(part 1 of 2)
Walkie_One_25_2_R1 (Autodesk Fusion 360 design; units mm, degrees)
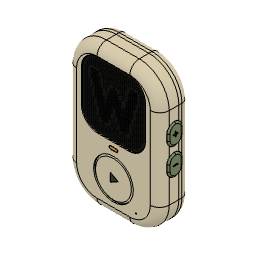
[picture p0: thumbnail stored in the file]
part number: 2026-09-08-11-10-29-672
part number: 2026-09-08-11-10-29-782
part number: 2026-09-08-11-10-30-391
part number: 2026-09-08-11-10-32-289
part number: 2026-09-08-11-10-32-713
part number: 2026-09-08-11-10-32-897
part number: 2026-09-08-11-10-33-663
part number: 2026-09-08-11-10-33-877
description: Part Number
part number: 2026-09-08-11-10-39-665
part number: 2026-09-08-11-10-39-844
part number: 2026-09-08-11-10-40-087
part number: 2026-09-08-11-10-40-640
part number: 2026-09-08-11-10-40-789
part number: 2026-09-08-11-10-41-055
part number: 2026-09-08-11-10-41-421
parameter "body_width" = 90.4 comment "25.2 R1 authoring dimension"
parameter "body_height" = 138.4 comment "25.2 R1 authoring dimension"
parameter "body_depth" = 28.8 comment "25.2 R1 authoring dimension"
parameter "grip_t" = 1.2 comment "25.2 R1 authoring dimension"
parameter "wall_t" = 2 comment "25.2 R1 authoring dimension"
parameter "corner_r" = 29.2 comment "25.2 R1 authoring dimension"
parameter "front_roll" = 9.2 comment "25.2 R1 authoring dimension"
parameter "rear_roll" = 7.2 comment "25.2 R1 authoring dimension"
parameter "play_diameter" = 38 comment "25.2 R1 authoring dimension"
parameter "play_y" = -36 comment "25.2 R1 authoring dimension"
parameter "grille_y" = 27.5 comment "25.2 R1 authoring dimension"
parameter "grille_t" = 0.8 comment "25.2 R1 authoring dimension"
work_plane "WorkPlane1" AlongDistance -13.2 (= "-( body_depth - 2 * grip_t ) / 2") ExtraOffset 0
sketch "rigid_envelope profile" plane through (0, 0, -13.2) normal (0, 0, 1) x axis (1, 0, 0)
  line L1 (-44, 68) -> (44, 68)
  line L2 (-44, -68) -> (-44, 68)
  line L3 (44, -68) -> (-44, -68)
  line L4 (44, 68) -> (44, -68)
  point P2 (44, 68)
  point P3 (-44, 68)
  point P4 (-44, -68)
  dimension "d15" distance P2 P3 = 88 (= "body_width - 2 * grip_t")
  dimension "d16" distance P3 P4 = 136 (= "body_height - 2 * grip_t")
extrude "Extrude1" new body sketch "rigid_envelope profile" along normal blind 26.4 (= "body_depth - 2 * grip_t")
fillet "Fillet1" radius 28 (= "corner_r - grip_t")
fillet "Fillet2" radius 8 (= "front_roll - grip_t")
fillet "Fillet3" radius 6 (= "rear_roll - grip_t")
work_plane "WorkPlane2" AlongDistance -11.2 (= "-( body_depth - 2 * ( grip_t + wall_t ) ) / 2") ExtraOffset 0
sketch "inner_cavity_tool profile" plane through (0, 0, -11.2) normal (0, 0, 1) x axis (1, 0, 0)
  line L1 (-42, 66) -> (42, 66)
  line L2 (-42, -66) -> (-42, 66)
  line L3 (42, -66) -> (-42, -66)
  line L4 (42, 66) -> (42, -66)
  point P2 (42, 66)
  point P3 (-42, 66)
  point P4 (-42, -66)
  dimension "d27" distance P2 P3 = 84 (= "body_width - 2 * ( grip_t + wall_t )")
  dimension "d28" distance P3 P4 = 132 (= "body_height - 2 * ( grip_t + wall_t )")
extrude "Extrude2" new body sketch "inner_cavity_tool profile" along normal blind 22.4 (= "body_depth - 2 * ( grip_t + wall_t )")
fillet "Fillet4" radius 26 (= "corner_r - grip_t - wall_t")
fillet "Fillet5" radius 6 (= "front_roll - grip_t - wall_t")
fillet "Fillet6" radius 4 (= "rear_roll - grip_t - wall_t")
combine "Combine1"
work_plane "WorkPlane3" AlongDistance 14 ExtraOffset 0
sketch "Flat rectangular grille mounting ledge" plane through (0, 0, 14) normal (0, 0, 1) x axis (1, 0, 0)
  line L1 (15, -4.8) -> (-15, -4.8)
  line L2 (31.3, 43.5) -> (31.3, 11.5)
  line L3 (-15, 59.8) -> (15, 59.8)
  line L4 (-31.3, 11.5) -> (-31.3, 43.5)
  arc A1 centre (15, 11.5) radius 16.3 clockwise from (31.3, 11.5) to (15, -4.8)
  arc A2 centre (15, 43.5) radius 16.3 clockwise from (15, 59.8) to (31.3, 43.5)
  arc A3 centre (-15, 43.5) radius 16.3 clockwise from (-31.3, 43.5) to (-15, 59.8)
  arc A4 centre (-15, 11.5) radius 16.3 clockwise from (-15, -4.8) to (-31.3, 11.5)
extrude "Extrude3" cut sketch "Flat rectangular grille mounting ledge" against normal blind 1.28
work_plane "WorkPlane4" AlongDistance 15 ExtraOffset 0
sketch "Full rectangular acoustic aperture" plane through (0, 0, 15) normal (0, 0, 1) x axis (1, 0, 0)
  line L1 (15, -2.3) -> (-15, -2.3)
  line L2 (28.8, 43.5) -> (28.8, 11.5)
  line L3 (-15, 57.3) -> (15, 57.3)
  line L4 (-28.8, 11.5) -> (-28.8, 43.5)
  arc A1 centre (15, 11.5) radius 13.8 clockwise from (28.8, 11.5) to (15, -2.3)
  arc A2 centre (15, 43.5) radius 13.8 clockwise from (15, 57.3) to (28.8, 43.5)
  arc A3 centre (-15, 43.5) radius 13.8 clockwise from (-28.8, 43.5) to (-15, 57.3)
  arc A4 centre (-15, 11.5) radius 13.8 clockwise from (-15, -2.3) to (-28.8, 11.5)
extrude "Extrude4" cut sketch "Full rectangular acoustic aperture" against normal blind 6
work_plane "WorkPlane5" AlongDistance 16 ExtraOffset 0
sketch "Play running clearance" plane through (0, 0, 16) normal (0, 0, 1) x axis (1, 0, 0)
  circle C1 centre (0, -36) radius 19.3
  dimension "d47" diameter C1 = 38.6 (= "play_diameter + 0.6 mm")
extrude "Extrude5" cut sketch "Play running clearance" against normal blind 8
work_plane "WorkPlane6" AlongDistance 11.3 ExtraOffset 0
sketch "Internal play flange relief" plane through (0, 0, 11.3) normal (0, 0, 1) x axis (1, 0, 0)
  circle C1 centre (0, -36) radius 20.5
  dimension "d52" diameter C1 = 41
extrude "Extrude6" cut sketch "Internal play flange relief" against normal blind 2
work_plane "WorkPlane7" AlongDistance 16 ExtraOffset 0
sketch "Status light opening" plane through (0, 0, 16) normal (0, 0, 1) x axis (1, 0, 0)
  line L1 (2.8, -12.05) -> (-2.8, -12.05)
  line L2 (4.3, -10.45) -> (4.3, -10.55)
  line L3 (-2.8, -8.95) -> (2.8, -8.95)
  line L4 (-4.3, -10.55) -> (-4.3, -10.45)
  arc A1 centre (2.8, -10.55) radius 1.5 clockwise from (4.3, -10.55) to (2.8, -12.05)
  arc A2 centre (2.8, -10.45) radius 1.5 clockwise from (2.8, -8.95) to (4.3, -10.45)
  arc A3 centre (-2.8, -10.45) radius 1.5 clockwise from (-4.3, -10.45) to (-2.8, -8.95)
  arc A4 centre (-2.8, -10.55) radius 1.5 clockwise from (-2.8, -12.05) to (-4.3, -10.55)
extrude "Extrude7" cut sketch "Status light opening" against normal blind 8
work_plane "WorkPlane8" AlongDistance -48 ExtraOffset 0
sketch "Left PTT aperture" plane through (-48, 0, 0) normal (1, 0, 0) x axis (0, 0, -1)
  line L1 (0.01, -36.3) -> (-0.01, -36.3)
  line L2 (7.8, 28.51) -> (7.8, -28.51)
  line L3 (-0.01, 36.3) -> (0.01, 36.3)
  line L4 (-7.8, -28.51) -> (-7.8, 28.51)
  arc A1 centre (0.01, -28.51) radius 7.79 clockwise from (7.8, -28.51) to (0.01, -36.3)
  arc A2 centre (0.01, 28.51) radius 7.79 clockwise from (0.01, 36.3) to (7.8, 28.51)
  arc A3 centre (-0.01, 28.51) radius 7.79 clockwise from (-7.8, 28.51) to (-0.01, 36.3)
  arc A4 centre (-0.01, -28.51) radius 7.79 clockwise from (-0.01, -36.3) to (-7.8, -28.51)
extrude "Extrude8" cut sketch "Left PTT aperture" along normal blind 10
work_plane "WorkPlane9" AlongDistance 48 ExtraOffset 0
sketch "Volume aperture 18" plane through (48, 0, 0) normal (1, 0, 0) x axis (0, 0, -1)
  line L1 (0.01, 7.7) -> (-0.01, 7.7)
  line L2 (7.3, 21.01) -> (7.3, 14.99)
  line L3 (-0.01, 28.3) -> (0.01, 28.3)
  line L4 (-7.3, 14.99) -> (-7.3, 21.01)
  arc A1 centre (0.01, 14.99) radius 7.29 clockwise from (7.3, 14.99) to (0.01, 7.7)
  arc A2 centre (0.01, 21.01) radius 7.29 clockwise from (0.01, 28.3) to (7.3, 21.01)
  arc A3 centre (-0.01, 21.01) radius 7.29 clockwise from (-7.3, 21.01) to (-0.01, 28.3)
  arc A4 centre (-0.01, 14.99) radius 7.29 clockwise from (-0.01, 7.7) to (-7.3, 14.99)
extrude "Extrude9" cut sketch "Volume aperture 18" against normal blind 10
work_plane "WorkPlane10" AlongDistance 48 ExtraOffset 0
sketch "Volume aperture -8" plane through (48, 0, 0) normal (1, 0, 0) x axis (0, 0, -1)
  line L1 (0.01, -18.3) -> (-0.01, -18.3)
  line L2 (7.3, -4.99) -> (7.3, -11.01)
  line L3 (-0.01, 2.3) -> (0.01, 2.3)
  line L4 (-7.3, -11.01) -> (-7.3, -4.99)
  arc A1 centre (0.01, -11.01) radius 7.29 clockwise from (7.3, -11.01) to (0.01, -18.3)
  arc A2 centre (0.01, -4.99) radius 7.29 clockwise from (0.01, 2.3) to (7.3, -4.99)
  arc A3 centre (-0.01, -4.99) radius 7.29 clockwise from (-7.3, -4.99) to (-0.01, 2.3)
  arc A4 centre (-0.01, -11.01) radius 7.29 clockwise from (-0.01, -18.3) to (-7.3, -11.01)
extrude "Extrude10" cut sketch "Volume aperture -8" against normal blind 10
work_plane "WorkPlane11" AlongDistance -48 ExtraOffset 0
sketch "USB service aperture" plane through (-48, 0, 0) normal (1, 0, 0) x axis (0, 0, -1)
  line L1 (7.35, -52.75) -> (3.85, -52.75)
  line L2 (9.35, -41.25) -> (9.35, -50.75)
  line L3 (3.85, -39.25) -> (7.35, -39.25)
  line L4 (1.85, -50.75) -> (1.85, -41.25)
  arc A1 centre (7.35, -50.75) radius 2 clockwise from (9.35, -50.75) to (7.35, -52.75)
  arc A2 centre (7.35, -41.25) radius 2 clockwise from (7.35, -39.25) to (9.35, -41.25)
  arc A3 centre (3.85, -41.25) radius 2 clockwise from (1.85, -41.25) to (3.85, -39.25)
  arc A4 centre (3.85, -50.75) radius 2 clockwise from (3.85, -52.75) to (1.85, -50.75)
extrude "Extrude11" cut sketch "USB service aperture" along normal blind 10
work_plane "WorkPlane12" AlongDistance 16 ExtraOffset 0
sketch "Microphone inlet" plane through (0, 0, 16) normal (0, 0, 1) x axis (1, 0, 0)
  circle C1 centre (22, -54) radius 0.6
  dimension "d77" diameter C1 = 1.2
extrude "Extrude12" cut sketch "Microphone inlet" against normal blind 8
work_plane "WorkPlane13" AlongDistance -4.2 ExtraOffset 0
split "Split1" bodies "structural_shell_front"
work_plane "WorkPlane1" AlongDistance -14.4 (= "-( body_depth ) / 2") ExtraOffset 0
sketch "skin_envelope profile" plane through (0, 0, -14.4) normal (0, 0, 1) x axis (1, 0, 0)
  line L1 (-45.2, 69.2) -> (45.2, 69.2)
  line L2 (-45.2, -69.2) -> (-45.2, 69.2)
  line L3 (45.2, -69.2) -> (-45.2, -69.2)
  line L4 (45.2, 69.2) -> (45.2, -69.2)
  point P2 (45.2, 69.2)
  point P3 (-45.2, 69.2)
  point P4 (-45.2, -69.2)
  dimension "d84" distance P2 P3 = 90.4 (= "body_width")
  dimension "d85" distance P3 P4 = 138.4 (= "body_height")
extrude "Extrude1" new body sketch "skin_envelope profile" along normal blind 28.8 (= "body_depth")
fillet "Fillet1" radius 29.2 (= "corner_r")
fillet "Fillet2" radius 9.2 (= "front_roll")
fillet "Fillet3" radius 7.2 (= "rear_roll")
work_plane "WorkPlane2" AlongDistance -13.2 (= "-( body_depth - 2 * grip_t ) / 2") ExtraOffset 0
sketch "skin_inner_tool profile" plane through (0, 0, -13.2) normal (0, 0, 1) x axis (1, 0, 0)
  line L1 (-44, 68) -> (44, 68)
  line L2 (-44, -68) -> (-44, 68)
  line L3 (44, -68) -> (-44, -68)
  line L4 (44, 68) -> (44, -68)
  point P2 (44, 68)
  point P3 (-44, 68)
  point P4 (-44, -68)
  dimension "d96" distance P2 P3 = 88 (= "body_width - 2 * grip_t")
  dimension "d97" distance P3 P4 = 136 (= "body_height - 2 * grip_t")
extrude "Extrude2" new body sketch "skin_inner_tool profile" along normal blind 26.4 (= "body_depth - 2 * grip_t")
fillet "Fillet4" radius 28 (= "corner_r - grip_t")
fillet "Fillet5" radius 8 (= "front_roll - grip_t")
fillet "Fillet6" radius 6 (= "rear_roll - grip_t")
combine "Combine1"
work_plane "WorkPlane3" AlongDistance 16 ExtraOffset 0
sketch "Recessed grille seat" plane through (0, 0, 16) normal (0, 0, 1) x axis (1, 0, 0)
  line L1 (15, -4.8) -> (-15, -4.8)
  line L2 (31.3, 43.5) -> (31.3, 11.5)
  line L3 (-15, 59.8) -> (15, 59.8)
  line L4 (-31.3, 11.5) -> (-31.3, 43.5)
  arc A1 centre (15, 11.5) radius 16.3 clockwise from (31.3, 11.5) to (15, -4.8)
  arc A2 centre (15, 43.5) radius 16.3 clockwise from (15, 59.8) to (31.3, 43.5)
  arc A3 centre (-15, 43.5) radius 16.3 clockwise from (-31.3, 43.5) to (-15, 59.8)
  arc A4 centre (-15, 11.5) radius 16.3 clockwise from (-15, -4.8) to (-31.3, 11.5)
extrude "Extrude3" cut sketch "Recessed grille seat" against normal blind 5
work_plane "WorkPlane4" AlongDistance 16 ExtraOffset 0
sketch "38 mm play opening" plane through (0, 0, 16) normal (0, 0, 1) x axis (1, 0, 0)
  circle C1 centre (0, -36) radius 19.3
  dimension "d112" diameter C1 = 38.6 (= "play_diameter + 0.6 mm")
extrude "Extrude4" cut sketch "38 mm play opening" against normal blind 8
work_plane "WorkPlane5" AlongDistance 16 ExtraOffset 0
sketch "Status lens opening" plane through (0, 0, 16) normal (0, 0, 1) x axis (1, 0, 0)
  line L1 (2.8, -12.05) -> (-2.8, -12.05)
  line L2 (4.3, -10.45) -> (4.3, -10.55)
  line L3 (-2.8, -8.95) -> (2.8, -8.95)
  line L4 (-4.3, -10.55) -> (-4.3, -10.45)
  arc A1 centre (2.8, -10.55) radius 1.5 clockwise from (4.3, -10.55) to (2.8, -12.05)
  arc A2 centre (2.8, -10.45) radius 1.5 clockwise from (2.8, -8.95) to (4.3, -10.45)
  arc A3 centre (-2.8, -10.45) radius 1.5 clockwise from (-4.3, -10.45) to (-2.8, -8.95)
  arc A4 centre (-2.8, -10.55) radius 1.5 clockwise from (-2.8, -12.05) to (-4.3, -10.55)
extrude "Extrude5" cut sketch "Status lens opening" against normal blind 8
work_plane "WorkPlane6" AlongDistance -48 ExtraOffset 0
sketch "PTT soft surround" plane through (-48, 0, 0) normal (1, 0, 0) x axis (0, 0, -1)
  line L1 (0.01, -36.3) -> (-0.01, -36.3)
  line L2 (7.8, 28.51) -> (7.8, -28.51)
  line L3 (-0.01, 36.3) -> (0.01, 36.3)
  line L4 (-7.8, -28.51) -> (-7.8, 28.51)
  arc A1 centre (0.01, -28.51) radius 7.79 clockwise from (7.8, -28.51) to (0.01, -36.3)
  arc A2 centre (0.01, 28.51) radius 7.79 clockwise from (0.01, 36.3) to (7.8, 28.51)
  arc A3 centre (-0.01, 28.51) radius 7.79 clockwise from (-7.8, 28.51) to (-0.01, 36.3)
  arc A4 centre (-0.01, -28.51) radius 7.79 clockwise from (-0.01, -36.3) to (-7.8, -28.51)
extrude "Extrude6" cut sketch "PTT soft surround" along normal blind 10
work_plane "WorkPlane7" AlongDistance 48 ExtraOffset 0
sketch "Volume soft surround 18" plane through (48, 0, 0) normal (1, 0, 0) x axis (0, 0, -1)
  line L1 (0.01, 7.7) -> (-0.01, 7.7)
  line L2 (7.3, 21.01) -> (7.3, 14.99)
  line L3 (-0.01, 28.3) -> (0.01, 28.3)
  line L4 (-7.3, 14.99) -> (-7.3, 21.01)
  arc A1 centre (0.01, 14.99) radius 7.29 clockwise from (7.3, 14.99) to (0.01, 7.7)
  arc A2 centre (0.01, 21.01) radius 7.29 clockwise from (0.01, 28.3) to (7.3, 21.01)
  arc A3 centre (-0.01, 21.01) radius 7.29 clockwise from (-7.3, 21.01) to (-0.01, 28.3)
  arc A4 centre (-0.01, 14.99) radius 7.29 clockwise from (-0.01, 7.7) to (-7.3, 14.99)
extrude "Extrude7" cut sketch "Volume soft surround 18" against normal blind 10
work_plane "WorkPlane8" AlongDistance 48 ExtraOffset 0
sketch "Volume soft surround -8" plane through (48, 0, 0) normal (1, 0, 0) x axis (0, 0, -1)
  line L1 (0.01, -18.3) -> (-0.01, -18.3)
  line L2 (7.3, -4.99) -> (7.3, -11.01)
  line L3 (-0.01, 2.3) -> (0.01, 2.3)
  line L4 (-7.3, -11.01) -> (-7.3, -4.99)
  arc A1 centre (0.01, -11.01) radius 7.29 clockwise from (7.3, -11.01) to (0.01, -18.3)
  arc A2 centre (0.01, -4.99) radius 7.29 clockwise from (0.01, 2.3) to (7.3, -4.99)
  arc A3 centre (-0.01, -4.99) radius 7.29 clockwise from (-7.3, -4.99) to (-0.01, 2.3)
  arc A4 centre (-0.01, -11.01) radius 7.29 clockwise from (-0.01, -18.3) to (-7.3, -11.01)
extrude "Extrude8" cut sketch "Volume soft surround -8" against normal blind 10
work_plane "WorkPlane9" AlongDistance -48 ExtraOffset 0
sketch "USB soft surround" plane through (-48, 0, 0) normal (1, 0, 0) x axis (0, 0, -1)
  line L1 (7.35, -52.75) -> (3.85, -52.75)
  line L2 (9.35, -41.25) -> (9.35, -50.75)
  line L3 (3.85, -39.25) -> (7.35, -39.25)
  line L4 (1.85, -50.75) -> (1.85, -41.25)
  arc A1 centre (7.35, -50.75) radius 2 clockwise from (9.35, -50.75) to (7.35, -52.75)
  arc A2 centre (7.35, -41.25) radius 2 clockwise from (7.35, -39.25) to (9.35, -41.25)
  arc A3 centre (3.85, -41.25) radius 2 clockwise from (1.85, -41.25) to (3.85, -39.25)
  arc A4 centre (3.85, -50.75) radius 2 clockwise from (3.85, -52.75) to (1.85, -50.75)
extrude "Extrude9" cut sketch "USB soft surround" along normal blind 10
work_plane "WorkPlane10" AlongDistance 16 ExtraOffset 0
sketch "Mic soft inlet" plane through (0, 0, 16) normal (0, 0, 1) x axis (1, 0, 0)
  circle C1 centre (22, -54) radius 0.6
  dimension "d137" diameter C1 = 1.2
extrude "Extrude10" cut sketch "Mic soft inlet" against normal blind 8
work_plane "WorkPlane11" AlongDistance -4.2 ExtraOffset 0
split "Split1" bodies "soft_grip_front"
work_plane "WorkPlane12" AlongDistance -14.5 ExtraOffset 0
sketch "Rear wordmark letter 0" plane through (0, 0, -14.5) normal (0, 0, 1) x axis (1, 0, 0)
  line L1 (22.5098, 5.989) -> (24, 5.9969)
  line L2 (21.8467, 3.0702) -> (22.5098, 5.989)
  line L3 (21.5858, 1.7488) -> (21.8467, 3.0702)
  line L4 (21.5574, 1.7102) -> (21.5858, 1.7488)
  line L5 (21.3097, 2.8815) -> (21.5574, 1.7102)
  line L6 (20.5712, 5.9363) -> (21.3097, 2.8815)
  line L7 (20.4693, 5.9969) -> (20.5712, 5.9363)
  line L8 (19.272, 5.9969) -> (20.4693, 5.9969)
  line L9 (19.1608, 5.948) -> (19.272, 5.9969)
  line L10 (18.4886, 3.1851) -> (19.1608, 5.948)
  line L11 (18.1709, 1.7226) -> (18.4886, 3.1851)
  line L12 (18.1426, 1.7532) -> (18.1709, 1.7226)
  line L13 (17.8488, 3.2206) -> (18.1426, 1.7532)
  line L14 (17.2147, 5.9925) -> (17.8488, 3.2206)
  line L15 (15.7262, 5.9934) -> (17.2147, 5.9925)
  line L16 (17.3134, 0.0663) -> (15.7262, 5.9934)
  line L17 (17.4146, 0.0031) -> (17.3134, 0.0663)
  line L18 (18.7615, 0.0031) -> (17.4146, 0.0031)
  line L19 (18.8779, 0.0459) -> (18.7615, 0.0031)
  line L20 (19.656, 3.0908) -> (18.8779, 0.0459)
  line L21 (19.8498, 3.9675) -> (19.656, 3.0908)
  line L22 (19.8776, 3.9612) -> (19.8498, 3.9675)
  line L23 (20.0372, 3.2302) -> (19.8776, 3.9612)
  line L24 (20.849, 0.0394) -> (20.0372, 3.2302)
  line L25 (20.9704, 0.0031) -> (20.849, 0.0394)
  line L26 (22.3173, 0.0031) -> (20.9704, 0.0031)
  line L27 (22.4165, 0.0688) -> (22.3173, 0.0031)
  line L28 (24, 5.9969) -> (22.4165, 0.0688)
extrude "Extrude11" cut sketch "Rear wordmark letter 0" along normal blind 0.35
work_plane "WorkPlane13" AlongDistance -14.5 ExtraOffset 0
sketch "Rear wordmark letter 1" plane through (0, 0, -14.5) normal (0, 0, 1) x axis (1, 0, 0)
  line L1 (12.8659, 5.9969) -> (14.6553, 5.9969)
  line L2 (12.8003, 5.8795) -> (12.8659, 5.9969)
  line L3 (10.7962, 0.1036) -> (12.8003, 5.8795)
  line L4 (10.804, 0.0031) -> (10.7962, 0.1036)
  line L5 (12.2952, 0.0031) -> (10.804, 0.0031)
  line L6 (12.6554, 1.1353) -> (12.2952, 0.0031)
  line L7 (12.7555, 1.2018) -> (12.6554, 1.1353)
  line L8 (14.8384, 1.1953) -> (12.7555, 1.2018)
  line L9 (15.2077, 0.061) -> (14.8384, 1.1953)
  line L10 (15.3147, 0.0031) -> (15.2077, 0.061)
  line L11 (16.6568, 0.0031) -> (15.3147, 0.0031)
  line L12 (16.7012, 0.0777) -> (16.6568, 0.0031)
  line L13 (14.6553, 5.9969) -> (16.7012, 0.0777)
  line L14 (13.7262, 4.6968) -> (13.1548, 2.7224)
  line L15 (13.7664, 4.6698) -> (13.7262, 4.6968)
  line L16 (14.475, 2.292) -> (13.7664, 4.6698)
  line L17 (13.1537, 2.292) -> (14.475, 2.292)
  line L18 (13.0214, 2.3027) -> (13.1537, 2.292)
  line L19 (13.1548, 2.7224) -> (13.0214, 2.3027)
extrude "Extrude12" cut sketch "Rear wordmark letter 1" along normal blind 0.35
work_plane "WorkPlane14" AlongDistance -14.5 ExtraOffset 0
sketch "Rear wordmark letter 2" plane through (0, 0, -14.5) normal (0, 0, 1) x axis (1, 0, 0)
  line L1 (9.2488, 5.9969) -> (10.5892, 5.9969)
  line L2 (9.2062, 5.8906) -> (9.2488, 5.9969)
  line L3 (9.2062, 1.2737) -> (9.2062, 5.8906)
  line L4 (9.1482, 1.1828) -> (9.2062, 1.2737)
  line L5 (6.6163, 1.1828) -> (9.1482, 1.1828)
  line L6 (6.5301, 1.1201) -> (6.6163, 1.1828)
  line L7 (6.5301, 0.0775) -> (6.5301, 1.1201)
  line L8 (6.6045, 0.0031) -> (6.5301, 0.0775)
  line L9 (10.4768, 0.0031) -> (6.6045, 0.0031)
  line L10 (10.5892, 0.0396) -> (10.4768, 0.0031)
  line L11 (10.5892, 5.9969) -> (10.5892, 0.0396)
extrude "Extrude13" cut sketch "Rear wordmark letter 2" along normal blind 0.35
work_plane "WorkPlane15" AlongDistance -14.5 ExtraOffset 0
sketch "Rear wordmark letter 3" plane through (0, 0, -14.5) normal (0, 0, 1) x axis (1, 0, 0)
  line L1 (4.8663, 5.9969) -> (6.2117, 5.9969)
  line L2 (4.8279, 5.8858) -> (4.8663, 5.9969)
  line L3 (4.8279, 3.3445) -> (4.8279, 5.8858)
  line L4 (4.7711, 3.3562) -> (4.8279, 3.3445)
  line L5 (2.6801, 5.8946) -> (4.7711, 3.3562)
  line L6 (2.5787, 5.9969) -> (2.6801, 5.8946)
  line L7 (1.0838, 5.9969) -> (2.5787, 5.9969)
  line L8 (0.9734, 5.9788) -> (1.0838, 5.9969)
  line L9 (3.0999, 3.47) -> (0.9734, 5.9788)
  line L10 (3.111, 3.351) -> (3.0999, 3.47)
  line L11 (0.9567, 0.1159) -> (3.111, 3.351)
  line L12 (0.8956, 0.0031) -> (0.9567, 0.1159)
  line L13 (2.3905, 0.0031) -> (0.8956, 0.0031)
  line L14 (2.5099, 0.0581) -> (2.3905, 0.0031)
  line L15 (4.0421, 2.4497) -> (2.5099, 0.0581)
  line L16 (4.1351, 2.3877) -> (4.0421, 2.4497)
  line L17 (4.8106, 1.5884) -> (4.1351, 2.3877)
  line L18 (4.8279, 1.4453) -> (4.8106, 1.5884)
  line L19 (4.8279, 0.0999) -> (4.8279, 1.4453)
  line L20 (4.8806, 0.0031) -> (4.8279, 0.0999)
  line L21 (6.0765, 0.0031) -> (4.8806, 0.0031)
  line L22 (6.2117, 0.0173) -> (6.0765, 0.0031)
  line L23 (6.2117, 5.9969) -> (6.2117, 0.0173)
extrude "Extrude14" cut sketch "Rear wordmark letter 3" along normal blind 0.35
work_plane "WorkPlane16" AlongDistance -14.5 ExtraOffset 0
sketch "Rear wordmark letter 4" plane through (0, 0, -14.5) normal (0, 0, 1) x axis (1, 0, 0)
  line L1 (0.6637, 0.0031) -> (-0.6775, 0.0031)
  line L2 (0.7055, 0.1104) -> (0.6637, 0.0031)
  line L3 (0.7055, 5.9224) -> (0.7055, 0.1104)
  line L4 (0.631, 5.9969) -> (0.7055, 5.9224)
  line L5 (-0.5613, 5.9969) -> (0.631, 5.9969)
  line L6 (-0.6775, 5.9641) -> (-0.5613, 5.9969)
  line L7 (-0.6775, 0.0031) -> (-0.6775, 5.9641)
extrude "Extrude15" cut sketch "Rear wordmark letter 4" along normal blind 0.35
work_plane "WorkPlane17" AlongDistance -14.5 ExtraOffset 0
sketch "Rear wordmark letter 5" plane through (0, 0, -14.5) normal (0, 0, 1) x axis (1, 0, 0)
  line L1 (-5.5663, 5.9969) -> (-1.2254, 5.9969)
  line L2 (-5.6399, 5.9209) -> (-5.5663, 5.9969)
  line L3 (-5.6399, 4.8731) -> (-5.6399, 5.9209)
  line L4 (-5.546, 4.8172) -> (-5.6399, 4.8731)
  line L5 (-2.702, 4.8172) -> (-5.546, 4.8172)
  line L6 (-2.6083, 4.7612) -> (-2.702, 4.8172)
  line L7 (-2.6083, 3.7134) -> (-2.6083, 4.7612)
  line L8 (-2.6371, 3.5925) -> (-2.6083, 3.7134)
  line L9 (-5.3314, 3.5925) -> (-2.6371, 3.5925)
  line L10 (-5.4094, 3.5207) -> (-5.3314, 3.5925)
  line L11 (-5.4094, 2.4729) -> (-5.4094, 3.5207)
  line L12 (-5.2863, 2.4463) -> (-5.4094, 2.4729)
  line L13 (-2.7416, 2.4463) -> (-5.2863, 2.4463)
  line L14 (-2.6083, 2.4299) -> (-2.7416, 2.4463)
  line L15 (-2.6083, 1.2324) -> (-2.6083, 2.4299)
  line L16 (-2.7084, 1.1828) -> (-2.6083, 1.2324)
  line L17 (-5.5524, 1.1828) -> (-2.7084, 1.1828)
  line L18 (-5.6399, 1.1205) -> (-5.5524, 1.1828)
  line L19 (-5.6399, 0.0727) -> (-5.6399, 1.1205)
  line L20 (-5.5598, 0.0031) -> (-5.6399, 0.0727)
  line L21 (-1.2254, 0.0095) -> (-5.5598, 0.0031)
  line L22 (-1.2254, 5.9969) -> (-1.2254, 0.0095)
extrude "Extrude16" cut sketch "Rear wordmark letter 5" along normal blind 0.35
work_plane "WorkPlane18" AlongDistance -14.5 ExtraOffset 0
sketch "Rear wordmark letter 6" plane through (0, 0, -14.5) normal (0, 0, 1) x axis (1, 0, 0)
  line L1 (-9.0257, 0.4782) -> (-9.267, 0.3033)
  line L2 (-8.9129, 0.5756) -> (-9.0257, 0.4782)
  line L3 (-8.7046, 0.7887) -> (-8.9129, 0.5756)
  line L4 (-8.5212, 1.0235) -> (-8.7046, 0.7887)
  line L5 (-8.3631, 1.2761) -> (-8.5212, 1.0235)
  line L6 (-8.2303, 1.5429) -> (-8.3631, 1.2761)
  line L7 (-8.1238, 1.8213) -> (-8.2303, 1.5429)
  line L8 (-8.0437, 2.1083) -> (-8.1238, 1.8213)
  line L9 (-7.9888, 2.4013) -> (-8.0437, 2.1083)
  line L10 (-7.9573, 2.6977) -> (-7.9888, 2.4013)
  line L11 (-7.9473, 2.9956) -> (-7.9573, 2.6977)
  line L12 (-7.9571, 3.2935) -> (-7.9473, 2.9956)
  line L13 (-7.988, 3.59) -> (-7.9571, 3.2935)
  line L14 (-8.0421, 3.883) -> (-7.988, 3.59)
  line L15 (-8.1213, 4.1704) -> (-8.0421, 3.883)
  line L16 (-8.2268, 4.4491) -> (-8.1213, 4.1704)
  line L17 (-8.3589, 4.7162) -> (-8.2268, 4.4491)
  line L18 (-8.5161, 4.9694) -> (-8.3589, 4.7162)
  line L19 (-8.6988, 5.2048) -> (-8.5161, 4.9694)
  line L20 (-8.7996, 5.3146) -> (-8.6988, 5.2048)
  line L21 (-9.0189, 5.5163) -> (-8.7996, 5.3146)
  line L22 (-9.2596, 5.692) -> (-9.0189, 5.5163)
  line L23 (-9.519, 5.8386) -> (-9.2596, 5.692)
  line L24 (-9.6549, 5.8998) -> (-9.519, 5.8386)
  line L25 (-9.9367, 5.9967) -> (-9.6549, 5.8998)
  line L26 (-10.2279, 6.0594) -> (-9.9367, 5.9967)
  line L27 (-10.5244, 6.0897) -> (-10.2279, 6.0594)
  line L28 (-10.8224, 6.0901) -> (-10.5244, 6.0897)
  line L29 (-11.119, 6.061) -> (-10.8224, 6.0901)
  line L30 (-11.4105, 5.9995) -> (-11.119, 6.061)
  line L31 (-11.6927, 5.9039) -> (-11.4105, 5.9995)
  line L32 (-11.8289, 5.8433) -> (-11.6927, 5.9039)
  line L33 (-12.0887, 5.6975) -> (-11.8289, 5.8433)
  line L34 (-12.3298, 5.5224) -> (-12.0887, 5.6975)
  line L35 (-12.5496, 5.3211) -> (-12.3298, 5.5224)
  line L36 (-12.7454, 5.0965) -> (-12.5496, 5.3211)
  line L37 (-12.916, 4.8522) -> (-12.7454, 5.0965)
  line L38 (-13.0615, 4.5921) -> (-12.916, 4.8522)
  line L39 (-13.1812, 4.3192) -> (-13.0615, 4.5921)
  line L40 (-13.2742, 4.036) -> (-13.1812, 4.3192)
  line L41 (-13.3414, 3.7457) -> (-13.2742, 4.036)
  line L42 (-13.3843, 3.4507) -> (-13.3414, 3.7457)
  line L43 (-13.405, 3.1534) -> (-13.3843, 3.4507)
  line L44 (-13.3983, 2.7064) -> (-13.405, 3.1534)
  line L45 (-13.3675, 2.4099) -> (-13.3983, 2.7064)
  line L46 (-13.3133, 2.1168) -> (-13.3675, 2.4099)
  line L47 (-13.2339, 1.8296) -> (-13.3133, 2.1168)
  line L48 (-13.1282, 1.5509) -> (-13.2339, 1.8296)
  line L49 (-12.9961, 1.2838) -> (-13.1282, 1.5509)
  line L50 (-12.8389, 1.0306) -> (-12.9961, 1.2838)
  line L51 (-12.6564, 0.7951) -> (-12.8389, 1.0306)
  line L52 (-12.4491, 0.5811) -> (-12.6564, 0.7951)
  line L53 (-12.2188, 0.3919) -> (-12.4491, 0.5811)
  line L54 (-11.9687, 0.23) -> (-12.2188, 0.3919)
  line L55 (-11.8368, 0.1606) -> (-11.9687, 0.23)
  line L56 (-11.5614, 0.0469) -> (-11.8368, 0.1606)
  line L57 (-11.2742, -0.0326) -> (-11.5614, 0.0469)
  line L58 (-10.9798, -0.0786) -> (-11.2742, -0.0326)
  line L59 (-10.6822, -0.0935) -> (-10.9798, -0.0786)
  line L60 (-10.3845, -0.0794) -> (-10.6822, -0.0935)
  line L61 (-10.09, -0.0341) -> (-10.3845, -0.0794)
  line L62 (-9.8026, 0.0447) -> (-10.09, -0.0341)
  line L63 (-9.5269, 0.1576) -> (-9.8026, 0.0447)
  line L64 (-9.267, 0.3033) -> (-9.5269, 0.1576)
  line L65 (-11.9033, 1.0644) -> (-11.6633, 0.8867)
  line L66 (-12.0113, 1.1677) -> (-11.9033, 1.0644)
  line L67 (-12.2016, 1.3979) -> (-12.0113, 1.1677)
  line L68 (-12.2838, 1.5228) -> (-12.2016, 1.3979)
  line L69 (-12.4232, 1.7871) -> (-12.2838, 1.5228)
  line L70 (-12.4794, 1.9256) -> (-12.4232, 1.7871)
  line L71 (-12.5649, 2.2119) -> (-12.4794, 1.9256)
  line L72 (-12.6345, 2.6546) -> (-12.5649, 2.2119)
  line L73 (-12.6486, 2.9532) -> (-12.6345, 2.6546)
  line L74 (-12.641, 3.252) -> (-12.6486, 2.9532)
  line L75 (-12.584, 3.6965) -> (-12.641, 3.252)
  line L76 (-12.5089, 3.9858) -> (-12.584, 3.6965)
  line L77 (-12.4585, 4.1265) -> (-12.5089, 3.9858)
  line L78 (-12.3988, 4.2636) -> (-12.4585, 4.1265)
  line L79 (-12.2533, 4.5245) -> (-12.3988, 4.2636)
  line L80 (-12.0741, 4.7635) -> (-12.2533, 4.5245)
  line L81 (-11.8603, 4.9721) -> (-12.0741, 4.7635)
  line L82 (-11.7411, 5.0623) -> (-11.8603, 4.9721)
  line L83 (-11.4826, 5.2119) -> (-11.7411, 5.0623)
  line L84 (-11.2033, 5.3177) -> (-11.4826, 5.2119)
  line L85 (-11.0581, 5.353) -> (-11.2033, 5.3177)
  line L86 (-10.7614, 5.3881) -> (-11.0581, 5.353)
  line L87 (-10.4629, 5.3784) -> (-10.7614, 5.3881)
  line L88 (-10.315, 5.3565) -> (-10.4629, 5.3784)
  line L89 (-10.0271, 5.277) -> (-10.315, 5.3565)
  line L90 (-9.8891, 5.2196) -> (-10.0271, 5.277)
  line L91 (-9.6291, 5.0727) -> (-9.8891, 5.2196)
  line L92 (-9.509, 4.9837) -> (-9.6291, 5.0727)
  line L93 (-9.2932, 4.7773) -> (-9.509, 4.9837)
  line L94 (-9.1981, 4.6619) -> (-9.2932, 4.7773)
  line L95 (-9.034, 4.4123) -> (-9.1981, 4.6619)
  line L96 (-8.9034, 4.1435) -> (-9.034, 4.4123)
  line L97 (-8.8519, 4.0032) -> (-8.9034, 4.1435)
  line L98 (-8.8092, 3.8599) -> (-8.8519, 4.0032)
  line L99 (-8.748, 3.5674) -> (-8.8092, 3.8599)
  line L100 (-8.7152, 3.2703) -> (-8.748, 3.5674)
  line L101 (-8.7062, 2.9715) -> (-8.7152, 3.2703)
  line L102 (-8.7189, 2.6728) -> (-8.7062, 2.9715)
  line L103 (-8.7565, 2.3763) -> (-8.7189, 2.6728)
  line L104 (-8.8234, 2.0851) -> (-8.7565, 2.3763)
  line L105 (-8.8694, 1.9428) -> (-8.8234, 2.0851)
  line L106 (-8.9244, 1.8039) -> (-8.8694, 1.9428)
  line L107 (-9.0618, 1.5385) -> (-8.9244, 1.8039)
  line L108 (-9.2327, 1.2934) -> (-9.0618, 1.5385)
  line L109 (-9.3311, 1.181) -> (-9.2327, 1.2934)
  line L110 (-9.5534, 0.9815) -> (-9.3311, 1.181)
  line L111 (-9.6763, 0.8964) -> (-9.5534, 0.9815)
  line L112 (-9.9407, 0.7574) -> (-9.6763, 0.8964)
  line L113 (-10.0804, 0.7044) -> (-9.9407, 0.7574)
  line L114 (-10.2241, 0.6631) -> (-10.0804, 0.7044)
  line L115 (-10.519, 0.6163) -> (-10.2241, 0.6631)
  line L116 (-10.8178, 0.615) -> (-10.519, 0.6163)
  line L117 (-10.9664, 0.6311) -> (-10.8178, 0.615)
  line L118 (-11.2573, 0.6987) -> (-10.9664, 0.6311)
  line L119 (-11.3976, 0.7503) -> (-11.2573, 0.6987)
  line L120 (-11.6633, 0.8867) -> (-11.3976, 0.7503)
extrude "Extrude17" cut sketch "Rear wordmark letter 6" along normal blind 0.35
work_plane "WorkPlane19" AlongDistance -14.5 ExtraOffset 0
sketch "Rear wordmark letter 7" plane through (0, 0, -14.5) normal (0, 0, 1) x axis (1, 0, 0)
  line L1 (-15.0333, 5.9969) -> (-14.2853, 5.9969)
  line L2 (-15.1658, 5.9659) -> (-15.0333, 5.9969)
  line L3 (-17.6459, 2.047) -> (-15.1658, 5.9659)
  line L4 (-18.1794, 1.146) -> (-17.6459, 2.047)
  line L5 (-18.2343, 1.0789) -> (-18.1794, 1.146)
  line L6 (-18.2115, 2.2754) -> (-18.2343, 1.0789)
  line L7 (-18.2115, 5.8659) -> (-18.2115, 2.2754)
  line L8 (-18.23, 5.9969) -> (-18.2115, 5.8659)
  line L9 (-18.9718, 5.9907) -> (-18.23, 5.9969)
  line L10 (-18.9718, 0.0066) -> (-18.9718, 5.9907)
  line L11 (-18.2273, 0.0031) -> (-18.9718, 0.0066)
  line L12 (-18.0875, 0.021) -> (-18.2273, 0.0031)
  line L13 (-15.9262, 3.4334) -> (-18.0875, 0.021)
  line L14 (-15.0725, 4.8401) -> (-15.9262, 3.4334)
  line L15 (-15.0102, 4.9215) -> (-15.0725, 4.8401)
  line L16 (-15.0416, 3.4259) -> (-15.0102, 4.9215)
  line L17 (-15.0416, 0.1346) -> (-15.0416, 3.4259)
  line L18 (-15.0235, 0.0031) -> (-15.0416, 0.1346)
  line L19 (-14.2853, 0.0128) -> (-15.0235, 0.0031)
  line L20 (-14.2853, 5.9969) -> (-14.2853, 0.0128)
extrude "Extrude18" cut sketch "Rear wordmark letter 7" along normal blind 0.35
work_plane "WorkPlane20" AlongDistance -14.5 ExtraOffset 0
sketch "Rear wordmark letter 8" plane through (0, 0, -14.5) normal (0, 0, 1) x axis (1, 0, 0)
  line L1 (-23.9675, 5.9969) -> (-20.0752, 5.9969)
  line L2 (-24, 5.8797) -> (-23.9675, 5.9969)
  line L3 (-24, 5.4306) -> (-24, 5.8797)
  line L4 (-23.9554, 5.3255) -> (-24, 5.4306)
  line L5 (-20.9612, 5.3255) -> (-23.9554, 5.3255)
  line L6 (-20.8335, 5.3036) -> (-20.9612, 5.3255)
  line L7 (-20.8335, 3.5071) -> (-20.8335, 5.3036)
  line L8 (-20.8806, 3.4045) -> (-20.8335, 3.5071)
  line L9 (-23.725, 3.4045) -> (-20.8806, 3.4045)
  line L10 (-23.7668, 3.2966) -> (-23.725, 3.4045)
  line L11 (-23.7668, 2.8475) -> (-23.7668, 3.2966)
  line L12 (-23.7298, 2.7348) -> (-23.7668, 2.8475)
  line L13 (-20.8854, 2.7348) -> (-23.7298, 2.7348)
  line L14 (-20.8335, 2.637) -> (-20.8854, 2.7348)
  line L15 (-20.8335, 0.6908) -> (-20.8335, 2.637)
  line L16 (-20.9668, 0.6745) -> (-20.8335, 0.6908)
  line L17 (-23.961, 0.6745) -> (-20.9668, 0.6745)
  line L18 (-24, 0.5638) -> (-23.961, 0.6745)
  line L19 (-24, 0.1147) -> (-24, 0.5638)
  line L20 (-23.9619, 0.0031) -> (-24, 0.1147)
  line L21 (-20.0752, 0.0087) -> (-23.9619, 0.0031)
  line L22 (-20.0752, 5.9969) -> (-20.0752, 0.0087)
extrude "Extrude19" cut sketch "Rear wordmark letter 8" along normal blind 0.35
work_plane "WorkPlane1" AlongDistance 11.2 ExtraOffset 0
sketch "play_key_38mm" plane through (0, 0, 11.2) normal (0, 0, 1) x axis (1, 0, 0)
  circle C1 centre (0, -36) radius 19
  dimension "d180" diameter C1 = 38 (= "play_diameter")
extrude "Extrude1" new body sketch "play_key_38mm" along normal blind 3.2 bodies "play_key_38mm"
fillet "Fillet1" radius 1.5
work_plane "WorkPlane2" AlongDistance 14.5 ExtraOffset 0
sketch "Play triangle engraving" plane through (0, 0, 14.5) normal (0, 0, 1) x axis (1, 0, 0)
  line L1 (-3.2, -31.9) -> (-3.2, -40.1)
  line L2 (4.5, -36) -> (-3.2, -31.9)
  line L3 (-3.2, -40.1) -> (4.5, -36)
extrude "Extrude2" cut sketch "Play triangle engraving" against normal blind 0.45
work_plane "WorkPlane3" AlongDistance 10.2 ExtraOffset 0
sketch "Play retention flange" plane through (0, 0, 10.2) normal (0, 0, 1) x axis (1, 0, 0)
  circle C1 centre (0, -36) radius 20.3
extrude "Extrude3" add sketch "Play retention flange" along normal blind 1.05
work_plane "WorkPlane4" AlongDistance 7.7 ExtraOffset 0
sketch "Play actuator stem" plane through (0, 0, 7.7) normal (0, 0, 1) x axis (1, 0, 0)
  circle C1 centre (0, -36) radius 2
  dimension "d195" diameter C1 = 4
extrude "Extrude4" add sketch "Play actuator stem" along normal blind 2.55
work_plane "WorkPlane1" AlongDistance -46.8 ExtraOffset 0
sketch "ptt_paddle_72mm" plane through (-46.8, 0, 0) normal (1, 0, 0) x axis (0, 0, -1)
  line L1 (0.01, -36) -> (-0.01, -36)
  line L2 (7.5, 28.51) -> (7.5, -28.51)
  line L3 (-0.01, 36) -> (0.01, 36)
  line L4 (-7.5, -28.51) -> (-7.5, 28.51)
  arc A1 centre (0.01, -28.51) radius 7.49 clockwise from (7.5, -28.51) to (0.01, -36)
  arc A2 centre (0.01, 28.51) radius 7.49 clockwise from (0.01, 36) to (7.5, 28.51)
  arc A3 centre (-0.01, 28.51) radius 7.49 clockwise from (-7.5, 28.51) to (-0.01, 36)
  arc A4 centre (-0.01, -28.51) radius 7.49 clockwise from (-0.01, -36) to (-7.5, -28.51)
extrude "Extrude1" new body sketch "ptt_paddle_72mm" along normal blind 4.8
fillet "Fillet1" radius 1.7
work_plane "WorkPlane1" AlongDistance 42 ExtraOffset 0
sketch "volume_plus" plane through (42, 0, 0) normal (1, 0, 0) x axis (0, 0, -1)
  line L1 (0.01, 8) -> (-0.01, 8)
  line L2 (7, 21.01) -> (7, 14.99)
  line L3 (-0.01, 28) -> (0.01, 28)
  line L4 (-7, 14.99) -> (-7, 21.01)
  arc A1 centre (0.01, 14.99) radius 6.99 clockwise from (7, 14.99) to (0.01, 8)
  arc A2 centre (0.01, 21.01) radius 6.99 clockwise from (0.01, 28) to (7, 21.01)
  arc A3 centre (-0.01, 21.01) radius 6.99 clockwise from (-7, 21.01) to (-0.01, 28)
  arc A4 centre (-0.01, 14.99) radius 6.99 clockwise from (-0.01, 8) to (-7, 14.99)
extrude "Extrude1" new body sketch "volume_plus" along normal blind 4.4
fillet "Fillet1" radius 1.5
work_plane "WorkPlane2" AlongDistance 46.5 ExtraOffset 0
sketch "volume_plus minus engraving" plane through (46.5, 0, 0) normal (1, 0, 0) x axis (0, 0, -1)
  line L1 (2.11, 17.6) -> (-2.11, 17.6)
  line L2 (2.5, 18.01) -> (2.5, 17.99)
  line L3 (-2.11, 18.4) -> (2.11, 18.4)
  line L4 (-2.5, 17.99) -> (-2.5, 18.01)
  arc A1 centre (2.11, 17.99) radius 0.39 clockwise from (2.5, 17.99) to (2.11, 17.6)
  arc A2 centre (2.11, 18.01) radius 0.39 clockwise from (2.11, 18.4) to (2.5, 18.01)
  arc A3 centre (-2.11, 18.01) radius 0.39 clockwise from (-2.5, 18.01) to (-2.11, 18.4)
  arc A4 centre (-2.11, 17.99) radius 0.39 clockwise from (-2.11, 17.6) to (-2.5, 17.99)
extrude "Extrude2" cut sketch "volume_plus minus engraving" against normal blind 0.5
work_plane "WorkPlane3" AlongDistance 46.5 ExtraOffset 0
sketch "volume_plus plus engraving" plane through (46.5, 0, 0) normal (1, 0, 0) x axis (0, 0, -1)
  line L1 (0.01, 15.5) -> (-0.01, 15.5)
  line L2 (0.4, 20.11) -> (0.4, 15.89)
  line L3 (-0.01, 20.5) -> (0.01, 20.5)
  line L4 (-0.4, 15.89) -> (-0.4, 20.11)
  arc A1 centre (0.01, 15.89) radius 0.39 clockwise from (0.4, 15.89) to (0.01, 15.5)
  arc A2 centre (0.01, 20.11) radius 0.39 clockwise from (0.01, 20.5) to (0.4, 20.11)
  arc A3 centre (-0.01, 20.11) radius 0.39 clockwise from (-0.4, 20.11) to (-0.01, 20.5)
  arc A4 centre (-0.01, 15.89) radius 0.39 clockwise from (-0.01, 15.5) to (-0.4, 15.89)
extrude "Extrude3" cut sketch "volume_plus plus engraving" against normal blind 0.5
work_plane "WorkPlane4" AlongDistance 42 ExtraOffset 0
sketch "volume_minus" plane through (42, 0, 0) normal (1, 0, 0) x axis (0, 0, -1)
  line L1 (0.01, -18) -> (-0.01, -18)
  line L2 (7, -4.99) -> (7, -11.01)
  line L3 (-0.01, 2) -> (0.01, 2)
  line L4 (-7, -11.01) -> (-7, -4.99)
  arc A1 centre (0.01, -11.01) radius 6.99 clockwise from (7, -11.01) to (0.01, -18)
  arc A2 centre (0.01, -4.99) radius 6.99 clockwise from (0.01, 2) to (7, -4.99)
  arc A3 centre (-0.01, -4.99) radius 6.99 clockwise from (-7, -4.99) to (-0.01, 2)
  arc A4 centre (-0.01, -11.01) radius 6.99 clockwise from (-0.01, -18) to (-7, -11.01)
extrude "Extrude4" new body sketch "volume_minus" along normal blind 4.4
fillet "Fillet2" radius 1.5
work_plane "WorkPlane5" AlongDistance 46.5 ExtraOffset 0
sketch "volume_minus minus engraving" plane through (46.5, 0, 0) normal (1, 0, 0) x axis (0, 0, -1)
  line L1 (2.11, -8.4) -> (-2.11, -8.4)
  line L2 (2.5, -7.99) -> (2.5, -8.01)
  line L3 (-2.11, -7.6) -> (2.11, -7.6)
  line L4 (-2.5, -8.01) -> (-2.5, -7.99)
  arc A1 centre (2.11, -8.01) radius 0.39 clockwise from (2.5, -8.01) to (2.11, -8.4)
  arc A2 centre (2.11, -7.99) radius 0.39 clockwise from (2.11, -7.6) to (2.5, -7.99)
  arc A3 centre (-2.11, -7.99) radius 0.39 clockwise from (-2.5, -7.99) to (-2.11, -7.6)
  arc A4 centre (-2.11, -8.01) radius 0.39 clockwise from (-2.11, -8.4) to (-2.5, -8.01)
extrude "Extrude5" cut sketch "volume_minus minus engraving" against normal blind 0.5
work_plane "WorkPlane1" AlongDistance 11 ExtraOffset 0
sketch "status_lens" plane through (0, 0, 11) normal (0, 0, 1) x axis (1, 0, 0)
  line L1 (2.751, -11.75) -> (-2.751, -11.75)
  line L2 (4, -10.499) -> (4, -10.501)
  line L3 (-2.751, -9.25) -> (2.751, -9.25)
  line L4 (-4, -10.501) -> (-4, -10.499)
  arc A1 centre (2.751, -10.501) radius 1.249 clockwise from (4, -10.501) to (2.751, -11.75)
  arc A2 centre (2.751, -10.499) radius 1.249 clockwise from (2.751, -9.25) to (4, -10.499)
  arc A3 centre (-2.751, -10.499) radius 1.249 clockwise from (-4, -10.499) to (-2.751, -9.25)
  arc A4 centre (-2.751, -10.501) radius 1.249 clockwise from (-2.751, -11.75) to (-4, -10.501)
extrude "Extrude1" new body sketch "status_lens" along normal blind 3.4 bodies "status_lens"
work_plane "WorkPlane1" AlongDistance 13 ExtraOffset 0
sketch "W_grille" plane through (0, 0, 13) normal (0, 0, 1) x axis (1, 0, 0)
  line L1 (15, -4.35) -> (-15, -4.35)
  line L2 (30.85, 43.5) -> (30.85, 11.5)
  line L3 (-15, 59.35) -> (15, 59.35)
  line L4 (-30.85, 11.5) -> (-30.85, 43.5)
  arc A1 centre (15, 11.5) radius 15.85 clockwise from (30.85, 11.5) to (15, -4.35)
  arc A2 centre (15, 43.5) radius 15.85 clockwise from (15, 59.35) to (30.85, 43.5)
  arc A3 centre (-15, 43.5) radius 15.85 clockwise from (-30.85, 43.5) to (-15, 59.35)
  arc A4 centre (-15, 11.5) radius 15.85 clockwise from (-15, -4.35) to (-30.85, 11.5)
extrude "Extrude1" new body sketch "W_grille" along normal blind 0.8 bodies "W_grille_0p8mm"
work_plane "WorkPlane2" AlongDistance 13.9 ExtraOffset 0
sketch "W artwork - individual through holes" plane through (0, 0, 13.9) normal (0, 0, 1) x axis (1, 0, 0)
  circle C1 centre (-28, 46.5) radius 0.45
  circle C2 centre (-28, 44.5) radius 0.45
  circle C3 centre (-28, 42.5) radius 0.45
  circle C4 centre (-28, 40.5) radius 0.45
  circle C5 centre (-28, 38.5) radius 0.45
  circle C6 centre (-28, 36.5) radius 0.45
  circle C7 centre (-28, 34.5) radius 0.45
  circle C8 centre (-28, 32.5) radius 0.45
  circle C9 centre (-28, 30.5) radius 0.45
  circle C10 centre (-28, 28.5) radius 0.45
  circle C11 centre (-28, 26.5) radius 0.45
  circle C12 centre (-28, 24.5) radius 0.45
  circle C13 centre (-28, 22.5) radius 0.45
  circle C14 centre (-28, 20.5) radius 0.45
  circle C15 centre (-28, 18.5) radius 0.45
  circle C16 centre (-28, 16.5) radius 0.45
  circle C17 centre (-28, 14.5) radius 0.45
  circle C18 centre (-28, 12.5) radius 0.45
  circle C19 centre (-28, 10.5) radius 0.45
  circle C20 centre (-28, 8.5) radius 0.45
  circle C21 centre (-26, 50.5) radius 0.45
  circle C22 centre (-26, 48.5) radius 0.45
  circle C23 centre (-26, 46.5) radius 0.45
  circle C24 centre (-26, 44.5) radius 0.45
  circle C25 centre (-26, 42.5) radius 0.45
  circle C26 centre (-26, 40.5) radius 0.45
  circle C27 centre (-26, 38.5) radius 0.45
  circle C28 centre (-26, 36.5) radius 0.45
  circle C29 centre (-26, 34.5) radius 0.45
  circle C30 centre (-26, 32.5) radius 0.45
  circle C31 centre (-26, 30.5) radius 0.45
  circle C32 centre (-26, 28.5) radius 0.45
  circle C33 centre (-26, 26.5) radius 0.45
  circle C34 centre (-26, 24.5) radius 0.45
  circle C35 centre (-26, 22.5) radius 0.45
  circle C36 centre (-26, 20.5) radius 0.45
  circle C37 centre (-26, 18.5) radius 0.45
  circle C38 centre (-26, 16.5) radius 0.45
  circle C39 centre (-26, 14.5) radius 0.45
  circle C40 centre (-26, 12.5) radius 0.45
  circle C41 centre (-26, 10.5) radius 0.45
  circle C42 centre (-26, 8.5) radius 0.45
  circle C43 centre (-26, 6.5) radius 0.45
  circle C44 centre (-26, 4.5) radius 0.45
  circle C45 centre (-24, 52.5) radius 0.45
  circle C46 centre (-24, 50.5) radius 0.45
  circle C47 centre (-24, 48.5) radius 0.45
  circle C48 centre (-24, 36.5) radius 0.45
  circle C49 centre (-24, 34.5) radius 0.45
  circle C50 centre (-24, 32.5) radius 0.45
  circle C51 centre (-24, 30.5) radius 0.45
  circle C52 centre (-24, 28.5) radius 0.45
  circle C53 centre (-24, 26.5) radius 0.45
  circle C54 centre (-24, 24.5) radius 0.45
  circle C55 centre (-24, 22.5) radius 0.45
  circle C56 centre (-24, 20.5) radius 0.45
  circle C57 centre (-24, 18.5) radius 0.45
  circle C58 centre (-24, 16.5) radius 0.45
  circle C59 centre (-24, 14.5) radius 0.45
  circle C60 centre (-24, 12.5) radius 0.45
  circle C61 centre (-24, 10.5) radius 0.45
  circle C62 centre (-24, 8.5) radius 0.45
  circle C63 centre (-24, 6.5) radius 0.45
  circle C64 centre (-24, 4.5) radius 0.45
  circle C65 centre (-24, 2.5) radius 0.45
  circle C66 centre (-22, 54.5) radius 0.45
  circle C67 centre (-22, 52.5) radius 0.45
  circle C68 centre (-22, 50.5) radius 0.45
  circle C69 centre (-22, 46.5) radius 0.55
  circle C70 centre (-22, 44.5) radius 0.55
  circle C71 centre (-22, 42.5) radius 0.55
  circle C72 centre (-22, 40.5) radius 0.55
  circle C73 centre (-22, 38.5) radius 0.55
  circle C74 centre (-22, 30.5) radius 0.45
  circle C75 centre (-22, 28.5) radius 0.45
  circle C76 centre (-22, 26.5) radius 0.45
  circle C77 centre (-22, 24.5) radius 0.45
  circle C78 centre (-22, 22.5) radius 0.45
  circle C79 centre (-22, 20.5) radius 0.45
  circle C80 centre (-22, 18.5) radius 0.45
  circle C81 centre (-22, 16.5) radius 0.45
  circle C82 centre (-22, 14.5) radius 0.45
  circle C83 centre (-22, 12.5) radius 0.45
  circle C84 centre (-22, 10.5) radius 0.45
  circle C85 centre (-22, 8.5) radius 0.45
  circle C86 centre (-22, 6.5) radius 0.45
  circle C87 centre (-22, 4.5) radius 0.45
  circle C88 centre (-22, 2.5) radius 0.45
  circle C89 centre (-22, 0.5) radius 0.45
  circle C90 centre (-20, 54.5) radius 0.45
  circle C91 centre (-20, 52.5) radius 0.45
  circle C92 centre (-20, 50.5) radius 0.45
  circle C93 centre (-20, 46.5) radius 0.625
  circle C94 centre (-20, 44.5) radius 0.7
  circle C95 centre (-20, 42.5) radius 0.7
  circle C96 centre (-20, 40.5) radius 0.7
  circle C97 centre (-20, 38.5) radius 0.625
  circle C98 centre (-20, 36.5) radius 0.625
  circle C99 centre (-20, 34.5) radius 0.55
  circle C100 centre (-20, 32.5) radius 0.55
  circle C101 centre (-20, 22.5) radius 0.45
  circle C102 centre (-20, 20.5) radius 0.45
  circle C103 centre (-20, 18.5) radius 0.45
  circle C104 centre (-20, 16.5) radius 0.45
  circle C105 centre (-20, 14.5) radius 0.45
  circle C106 centre (-20, 12.5) radius 0.45
  circle C107 centre (-20, 10.5) radius 0.45
  circle C108 centre (-20, 8.5) radius 0.45
  circle C109 centre (-20, 6.5) radius 0.45
  circle C110 centre (-20, 4.5) radius 0.45
  circle C111 centre (-20, 2.5) radius 0.45
  circle C112 centre (-20, 0.5) radius 0.45
  circle C113 centre (-18, 56.5) radius 0.45
  circle C114 centre (-18, 54.5) radius 0.45
  circle C115 centre (-18, 52.5) radius 0.45
  circle C116 centre (-18, 50.5) radius 0.45
  circle C117 centre (-18, 46.5) radius 0.625
  circle C118 centre (-18, 44.5) radius 0.7
  circle C119 centre (-18, 42.5) radius 0.7
  circle C120 centre (-18, 40.5) radius 0.7
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extrude "Extrude2" cut sketch "W artwork - individual through holes" against normal blind 1
work_plane "WorkPlane1" AlongDistance 12.85 ExtraOffset 0
sketch "acoustic_cloth_full_area_REFERENCE" plane through (0, 0, 12.85) normal (0, 0, 1) x axis (1, 0, 0)
  line L1 (15, -4.25) -> (-15, -4.25)
  line L2 (30.75, 43.5) -> (30.75, 11.5)
  line L3 (-15, 59.25) -> (15, 59.25)
  line L4 (-30.75, 11.5) -> (-30.75, 43.5)
  arc A1 centre (15, 11.5) radius 15.75 clockwise from (30.75, 11.5) to (15, -4.25)
  arc A2 centre (15, 43.5) radius 15.75 clockwise from (15, 59.25) to (30.75, 43.5)
  arc A3 centre (-15, 43.5) radius 15.75 clockwise from (-30.75, 43.5) to (-15, 59.25)
  arc A4 centre (-15, 11.5) radius 15.75 clockwise from (-15, -4.25) to (-30.75, 11.5)
extrude "Extrude1" new body sketch "acoustic_cloth_full_area_REFERENCE" along normal blind 0.15 bodies "acoustic_cloth_full_area_REFERENCE"
work_plane "WorkPlane1" AlongDistance 12.72 ExtraOffset 0
sketch "Perimeter PSA ring" plane through (0, 0, 12.72) normal (0, 0, 1) x axis (1, 0, 0)
  line L1 (15, -4.15) -> (-15, -4.15)
  line L2 (30.65, 43.5) -> (30.65, 11.5)
  line L3 (-15, 59.15) -> (15, 59.15)
  line L4 (-30.65, 11.5) -> (-30.65, 43.5)
  line L5 (15, -2.65) -> (-15, -2.65)
  line L6 (29.15, 43.5) -> (29.15, 11.5)
  line L7 (-15, 57.65) -> (15, 57.65)
  line L8 (-29.15, 11.5) -> (-29.15, 43.5)
  arc A1 centre (15, 11.5) radius 15.65 clockwise from (30.65, 11.5) to (15, -4.15)
  arc A2 centre (15, 43.5) radius 15.65 clockwise from (15, 59.15) to (30.65, 43.5)
  arc A3 centre (-15, 43.5) radius 15.65 clockwise from (-30.65, 43.5) to (-15, 59.15)
  arc A4 centre (-15, 11.5) radius 15.65 clockwise from (-15, -4.15) to (-30.65, 11.5)
  arc A5 centre (15, 11.5) radius 14.15 clockwise from (29.15, 11.5) to (15, -2.65)
  arc A6 centre (15, 43.5) radius 14.15 clockwise from (15, 57.65) to (29.15, 43.5)
  arc A7 centre (-15, 43.5) radius 14.15 clockwise from (-29.15, 43.5) to (-15, 57.65)
  arc A8 centre (-15, 11.5) radius 14.15 clockwise from (-15, -2.65) to (-29.15, 11.5)
extrude "Extrude1" new body sketch "Perimeter PSA ring" along normal blind 0.13 bodies "grille_perimeter_PSA_REFERENCE"
work_plane "WorkPlane1" AlongDistance 4.8 ExtraOffset 0
sketch "Switch carrier open center" plane through (0, 0, 4.8) normal (0, 0, 1) x axis (1, 0, 0)
  line L1 (12.5, -48.5) -> (-12.5, -48.5)
  line L2 (15.5, -26.5) -> (15.5, -45.5)
  line L3 (-12.5, -23.5) -> (12.5, -23.5)
  line L4 (-15.5, -45.5) -> (-15.5, -26.5)
  line L5 (5.2, -42.2) -> (-5.2, -42.2)
  line L6 (6.2, -30.8) -> (6.2, -41.2)
  line L7 (-5.2, -29.8) -> (5.2, -29.8)
  line L8 (-6.2, -41.2) -> (-6.2, -30.8)
  arc A1 centre (12.5, -45.5) radius 3 clockwise from (15.5, -45.5) to (12.5, -48.5)
  arc A2 centre (12.5, -26.5) radius 3 clockwise from (12.5, -23.5) to (15.5, -26.5)
  arc A3 centre (-12.5, -26.5) radius 3 clockwise from (-15.5, -26.5) to (-12.5, -23.5)
  arc A4 centre (-12.5, -45.5) radius 3 clockwise from (-12.5, -48.5) to (-15.5, -45.5)
  arc A5 centre (5.2, -41.2) radius 1 clockwise from (6.2, -41.2) to (5.2, -42.2)
  arc A6 centre (5.2, -30.8) radius 1 clockwise from (5.2, -29.8) to (6.2, -30.8)
  arc A7 centre (-5.2, -30.8) radius 1 clockwise from (-6.2, -30.8) to (-5.2, -29.8)
  arc A8 centre (-5.2, -41.2) radius 1 clockwise from (-5.2, -42.2) to (-6.2, -41.2)
extrude "Extrude1" new body sketch "Switch carrier open center" along normal blind 1.6 bodies "play_switch_carrier"
work_plane "WorkPlane2" AlongDistance 7 ExtraOffset 0
sketch "Carrier screw clearance" plane through (0, 0, 7) normal (0, 0, 1) x axis (1, 0, 0)
  circle C1 centre (-12, -36) radius 1.2
  dimension "d254" diameter C1 = 2.4
extrude "Extrude2" cut sketch "Carrier screw clearance" against normal blind 3
work_plane "WorkPlane3" AlongDistance 7 ExtraOffset 0
sketch "Carrier screw clearance (1)" plane through (0, 0, 7) normal (0, 0, 1) x axis (1, 0, 0)
  circle C1 centre (12, -36) radius 1.2
  dimension "d259" diameter C1 = 2.4
extrude "Extrude3" cut sketch "Carrier screw clearance (1)" against normal blind 3
work_plane "WorkPlane1" AlongDistance 3.5 ExtraOffset 0
sketch "Speaker retaining annulus" plane through (0, 0, 3.5) normal (0, 0, 1) x axis (1, 0, 0)
  circle C1 centre (0, 27.5) radius 21.6
  circle C2 centre (0, 27.5) radius 20.25
extrude "Extrude1" new body sketch "Speaker retaining annulus" along normal blind 6 bodies "speaker_edge_cradle"
work_plane "WorkPlane1" AlongDistance -5.8 ExtraOffset 0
